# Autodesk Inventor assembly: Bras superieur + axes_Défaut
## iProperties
Shininess: 64.0
Length Units: 11269
Angle Units: 11279
Time Units: 11290
Mass Units: 11283
Length Display Precision: 3
Angle Display Precision: 2
Compacted: True
Created: 2006-11
Part Number: Bras superieur + axes_Défaut
Document SubType Name: Assembly
Designer: profs_sti
Density: 0.0
Volumn: 0.0
Area: 0.0
PropertySet Name: Model Information
Control State: 0
Master: False
Checked Out: False
Author: profs_sti
